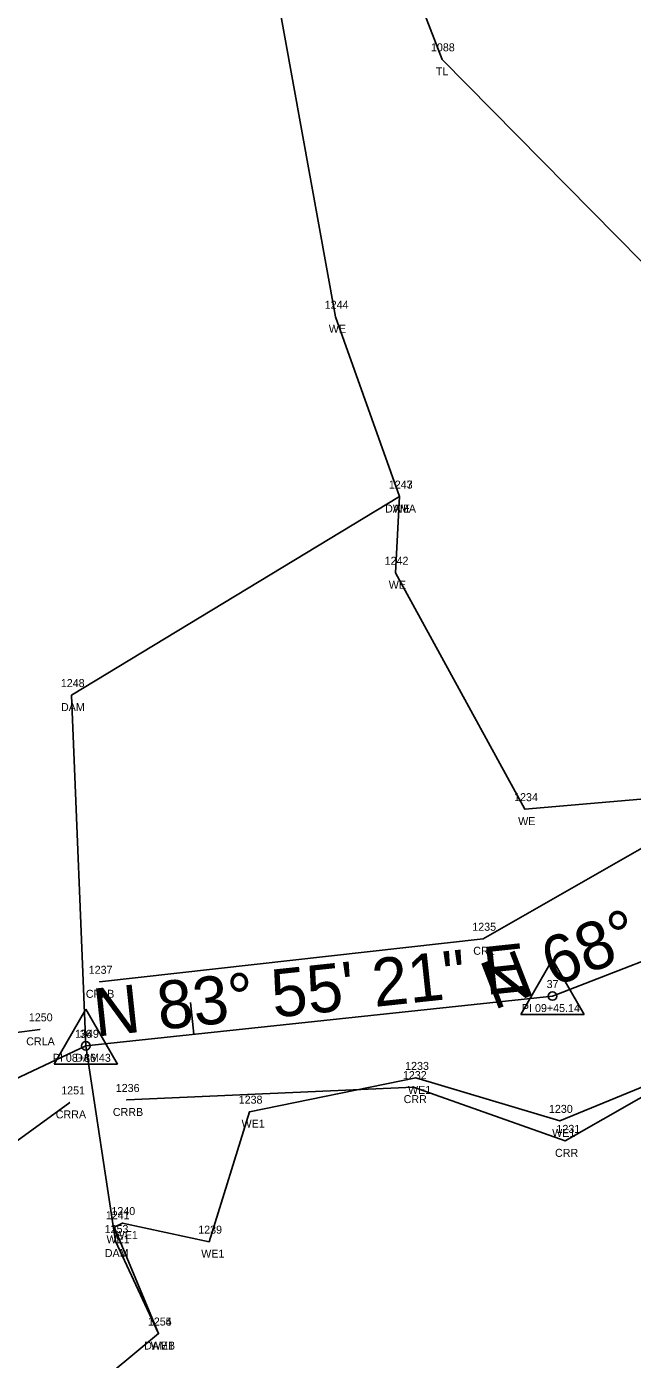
# Model space of a CAD drawing. Extents: x 2445178 to 2446205, y 790762 to 792372.
# Drawn here: x 2445595.7 to 2445671.4, y 791731.8 to 791898.3 of the extents above; entities that cross this region are included whole.
import ezdxf

# ---------------------------------------------------------------- set-up
doc = ezdxf.new("R2010")
doc.units = 0
for name, color, linetype in [('RD_EX_Dam', 7, 'Continuous'), ('RD_EX_Dam_txCode', 7, 'Continuous'), ('RD_EX_H2O', 7, 'Continuous'), ('RD_EX_H2O_txCode', 7, 'Continuous'), ('RD_EX_VEG', 7, 'Continuous'), ('RD_EX_VEG_txCode', 7, 'Continuous'), ('RD_HC_Cl', 7, 'Continuous'), ('RD_HC_Data', 7, 'Continuous'), ('RD_HC_Data_Tic', 7, 'Continuous'), ('RD_HC_txCode', 7, 'Continuous'), ('RD_SMD_Locator', 7, 'Continuous')]:
    doc.layers.add(name, color=color, linetype=linetype)

msp = doc.modelspace()

# ---------------------------------------------------------------- linework, layer by layer
at = {"layer": 'RD_EX_Dam'}
msp.add_lwpolyline([(2445642.32, 791839.59), (2445601.3, 791814.78), (2445603.08, 791770.94), (2445606.78, 791746.54), (2445612.18, 791734.98)], dxfattribs=at)
at = {"layer": 'RD_EX_H2O'}
for points in [[(2445757.3, 791817.48), (2445724.23, 791814.58), (2445698.23, 791807.38), (2445689.87, 791803.29), (2445658, 791800.52), (2445641.81, 791830.07), (2445642.32, 791839.59), (2445634.31, 791862.06), (2445625.81, 791909.02), (2445601.16, 791980.42)], [(2445696.27, 791809.15), (2445652.77, 791784.32), (2445604.79, 791778.94)], [(2445748.32, 791780.49), (2445701.12, 791774.43), (2445677.09, 791767.59), (2445662.39, 791761.56), (2445644.36, 791766.93), (2445623.55, 791762.71), (2445618.49, 791746.46), (2445607.67, 791748.78), (2445606.64, 791748.27), (2445612.18, 791734.98), (2445561.56, 791692.97), (2445554.1, 791670.89), (2445517.8, 791656.91), (2445473.7, 791621.85), (2445363.77, 791592.3), (2445292.26, 791558.82)], [(2445746.88, 791778.25), (2445701.7, 791773.05), (2445676.99, 791767.02), (2445663.02, 791759.06), (2445644.08, 791765.78), (2445608.19, 791764.17)], [(2445597.34, 791773), (2445578, 791770.46), (2445544.99, 791749.08)], [(2445601.06, 791763.87), (2445588.04, 791754.39), (2445544.11, 791733.92), (2445501.1, 791687.67), (2445464.95, 791685.09), (2445422.11, 791733.61), (2445413.32, 791729.6), (2445404.23, 791718.68), (2445377.21, 791675.18), (2445369.95, 791673.71), (2445335.95, 791691.26), (2445308.99, 791685.23), (2445308.22, 791596.59), (2445306.48, 791581.14), (2445293.31, 791557.11)]]:
    msp.add_lwpolyline(points, dxfattribs=at)
at = {"layer": 'RD_EX_VEG'}
msp.add_lwpolyline([(2445687.12, 791815.07), (2445675.71, 791865.82), (2445647.64, 791894.24), (2445625.38, 791951.76), (2445599.8, 791999.43), (2445616.22, 792074.95), (2445645.15, 792198.05), (2445661.49, 792301.38)], dxfattribs=at)
at = {"layer": 'RD_HC_Cl'}
for p, q in [((2445661.45, 791777.16), (2445699.64, 791791.97)), ((2445603.08, 791770.94), (2445661.45, 791777.16)), ((2445541.89, 791742.03), (2445603.08, 791770.94))]:
    msp.add_line(p, q, dxfattribs=at)
at = {"layer": 'RD_HC_Data'}
for p, q in [((2445657.48, 791774.86), (2445661.45, 791781.74)), ((2445661.45, 791781.74), (2445665.42, 791774.86)), ((2445599.11, 791768.65), (2445603.08, 791775.53)), ((2445603.08, 791775.53), (2445607.05, 791768.65)), ((2445657.48, 791774.86), (2445665.42, 791774.86)), ((2445599.11, 791768.65), (2445607.05, 791768.65))]:
    msp.add_line(p, q, dxfattribs=at)
for centre in [(2445661.45, 791777.16), (2445603.08, 791770.94)]:
    msp.add_circle(centre, 0.529, dxfattribs=at)
at = {"layer": 'RD_HC_Data_Tic'}
msp.add_line((2445616.57, 791772.38), (2445616.15, 791776.35), dxfattribs=at)
at = {"layer": 'RD_SMD_Locator'}
for centre in [(2445647.64, 791894.24), (2445634.31, 791862.06), (2445642.32, 791839.59), (2445642.32, 791839.59), (2445641.81, 791830.07), (2445601.3, 791814.78), (2445658, 791800.52), (2445652.77, 791784.32), (2445604.79, 791778.94), (2445661.45, 791777.16), (2445597.34, 791773), (2445603.08, 791770.94), (2445603.08, 791770.94), (2445644.36, 791766.93), (2445644.08, 791765.78), (2445601.06, 791763.87), (2445608.19, 791764.17), (2445623.55, 791762.71), (2445662.39, 791761.56), (2445663.02, 791759.06), (2445606.64, 791748.27), (2445607.67, 791748.78), (2445606.78, 791746.54), (2445618.49, 791746.46), (2445612.18, 791734.98), (2445612.18, 791734.98)]:
    msp.add_circle(centre, 0.001, dxfattribs=at)

# ---------------------------------------------------------------- texts
at = {"layer": 'RD_EX_Dam_txCode'}
for s, p in [('1247', (2445640.98, 791840.59)), ('DAMA', (2445640.51, 791837.59)), ('1248', (2445599.95, 791815.78)), ('DAM', (2445599.97, 791812.78)), ('1249', (2445601.73, 791771.94)), ('DAM', (2445601.75, 791768.94)), ('1253', (2445605.43, 791747.54)), ('DAM', (2445605.45, 791744.54)), ('1254', (2445610.84, 791735.98)), ('DAMB', (2445610.38, 791732.98))]:
    msp.add_text(s, height=1, dxfattribs=at).set_placement(p)
at = {"layer": 'RD_EX_H2O_txCode'}
for s, p in [('1244', (2445632.96, 791863.06)), ('WE', (2445633.47, 791860.06)), ('1243', (2445640.98, 791840.59)), ('WE', (2445641.49, 791837.59)), ('1242', (2445640.46, 791831.07)), ('WE', (2445640.97, 791828.07)), ('1234', (2445656.65, 791801.52)), ('WE', (2445657.16, 791798.52)), ('1235', (2445651.42, 791785.32)), ('CRL', (2445651.54, 791782.32)), ('1237', (2445603.44, 791779.94)), ('CRLB', (2445603.08, 791776.94)), ('1250', (2445595.95, 791774)), ('CRLA', (2445595.62, 791771)), ('1233', (2445643.02, 791767.93)), ('1232', (2445642.74, 791766.78)), ('1251', (2445600, 791764.87)), ('1236', (2445606.82, 791765.17)), ('CRR', (2445642.83, 791763.78)), ('WE1', (2445643.38, 791764.93)), ('CRRB', (2445606.46, 791762.17)), ('1238', (2445622.2, 791763.71)), ('1230', (2445661.01, 791762.56)), ('CRRA', (2445599.32, 791761.87)), ('WE1', (2445622.56, 791760.71)), ('WE1', (2445661.41, 791759.56)), ('1231', (2445661.95, 791760.06)), ('CRR', (2445661.77, 791757.06)), ('1241', (2445605.58, 791749.27)), ('1240', (2445606.28, 791749.78)), ('1239', (2445617.14, 791747.46)), ('WE1', (2445605.66, 791746.27)), ('WE1', (2445606.68, 791746.78)), ('WE1', (2445617.51, 791744.46)), ('1255', (2445610.84, 791735.98)), ('WE1', (2445611.2, 791732.98))]:
    msp.add_text(s, height=1, dxfattribs=at).set_placement(p)
at = {"layer": 'RD_EX_VEG_txCode'}
for s, p in [('1088', (2445646.25, 791895.24)), ('TL', (2445646.86, 791892.24))]:
    msp.add_text(s, height=1, dxfattribs=at).set_placement(p)
at = {"layer": 'RD_HC_Data'}
for s, rotation, p in [('N 68%%d 48\' 15" E', 21.1959, (2445654.1, 791775.38)), ('N 83%%d 55\' 21" E', 6.0774, (2445604.34, 791772.08))]:
    msp.add_text(s, height=6, rotation=rotation, dxfattribs=at).set_placement(p)
at = {"layer": 'RD_HC_txCode'}
for s, p in [('37', (2445660.72, 791778.16)), ('PI 09+45.14', (2445657.63, 791775.16)), ('36', (2445602.32, 791771.94)), ('PI 08+86.43', (2445598.95, 791768.94))]:
    msp.add_text(s, height=1, dxfattribs=at).set_placement(p)

doc.saveas('drawing.dxf')
